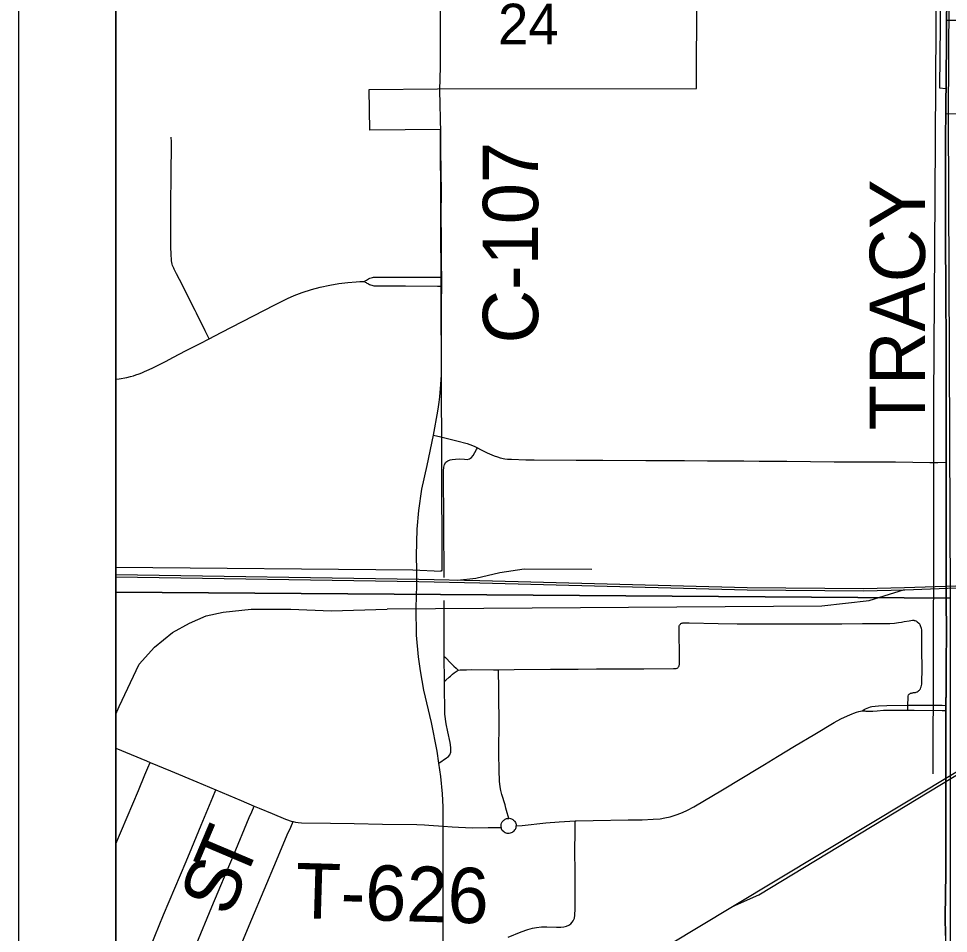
# Model space of a CAD drawing. Extents: x 0 to 40.2, y 0 to 22.
# Drawn here: x 2 to 2.955, y 15.414 to 16.354 of the extents above; entities that cross this region are included whole.
import ezdxf

# ---------------------------------------------------------------- set-up
doc = ezdxf.new("R2010")
doc.units = 0
for name, color, linetype in [('GM_X_Adjacent_County', 7, 'Continuous'), ('GM_X_City_Street', 7, 'Continuous'), ('GM_X_Corporation', 7, 'Continuous'), ('GM_X_County_Road_Text', 7, 'Continuous'), ('GM_X_Major_Lake_Text', 7, 'Continuous'), ('GM_X_Major_River', 7, 'Continuous'), ('GM_X_Minor_Lake', 7, 'Continuous'), ('GM_X_Rail_Line', 7, 'Continuous'), ('GM_X_Rail_Line_Text', 7, 'Continuous'), ('GM_X_Township_Road', 7, 'Continuous'), ('GM_X_Unincorporated_Location', 7, 'Continuous')]:
    doc.layers.add(name, color=color, linetype=linetype)

msp = doc.modelspace()

# ---------------------------------------------------------------- linework, layer by layer
at = {"layer": 'GM_X_Adjacent_County'}
for p, q in [((2, 21), (2, 14)), ((2.1, 20.9), (2.1, 14.1))]:
    msp.add_line(p, q, dxfattribs=at)
at = {"layer": 'GM_X_Corporation'}
for points in [[(2.1, 17.42646), (2.1, 14.1), (8.77357, 14.1)], [(2.1, 17.42646), (2.1, 14.1)], [(2.1, 16.79991), (2.1, 15.79032), (2.40476, 15.78728), (2.43404, 15.78611), (2.43404, 15.78684), (2.43478, 15.78683), (2.43443, 15.90141), (2.43329, 16.2397), (2.36065, 16.23885), (2.36014, 16.2807), (2.43027, 16.28139), (2.69598, 16.28187), (2.69674, 16.47681)], [(2.94777, 16.47691), (2.94574, 16.28254), (2.95227, 16.28186), (2.95199, 16.25577), (3.76676, 16.25602)], [(2.95339, 16.38497), (2.95296, 16.35249), (2.95273, 16.33553), (2.95228, 16.2871), (2.95225, 16.26721), (2.95199, 16.25577), (2.95187, 16.23333), (2.95182, 16.20037), (2.95173, 16.16556), (2.95187, 16.13695), (2.95186, 16.10961), (2.95198, 16.09219), (2.95217, 16.06609), (2.95237, 16.02442), (2.95249, 16.00591), (2.95234, 15.98044), (2.95244, 15.92634), (2.95237, 15.89849), (2.95237, 15.89713), (2.95254, 15.84302), (2.95231, 15.82625), (2.9526, 15.80324), (2.95241, 15.7765), (2.95245, 15.76531), (2.95255, 15.74826), (2.95265, 15.73145), (2.95247, 15.68297), (2.95241, 15.66431), (2.95222, 15.64879), (2.95216, 15.64356), (2.95202, 15.63261), (2.95214, 15.59965), (2.95203, 15.58162), (2.95194, 15.57043), (2.95195, 15.56113), (2.9521, 15.55057), (2.95227, 15.5319), (2.95195, 15.47593), (2.95154, 15.43118), (2.95171, 15.41189)], [(2.95171, 15.41189), (2.95154, 15.43118), (2.95195, 15.47593), (2.95227, 15.5319), (2.9521, 15.55057), (2.95195, 15.56113), (2.95194, 15.57043), (2.95203, 15.58162), (2.95214, 15.59965), (2.95202, 15.63261), (2.95216, 15.64356), (2.95222, 15.64879), (2.95241, 15.66431), (2.95247, 15.68297), (2.95265, 15.73145), (2.95255, 15.74826), (2.95245, 15.76531), (2.95241, 15.7765), (2.9526, 15.80324), (2.95231, 15.82625), (2.95254, 15.84302), (2.95237, 15.89713), (2.95237, 15.89849), (2.95244, 15.92634), (2.95234, 15.98044), (2.95249, 16.00591), (2.95237, 16.02442), (2.95217, 16.06609), (2.95198, 16.09219), (2.95186, 16.10961), (2.95187, 16.13695), (2.95173, 16.16556), (2.95182, 16.20037), (2.95187, 16.23333), (2.95199, 16.25577), (2.95225, 16.26721), (2.95228, 16.2871), (2.95273, 16.33553), (2.95296, 16.35249), (2.95339, 16.38497)]]:
    msp.add_lwpolyline(points, dxfattribs=at)
for points in [[(2.1, 16.80277), (2.1, 15.76442), (2.95674, 15.75847), (2.95497, 16.25386), (2.95786, 16.79166), (2.43037, 16.80164), (2.18336, 16.80457)], [(2.1, 15.76442), (2.1, 14.73705), (2.95186, 14.72799), (2.9569, 15.35216), (2.95674, 15.75847)]]:
    msp.add_lwpolyline(points, close=True, dxfattribs=at)
at = {"layer": 'GM_X_Major_Lake_Text'}
for p, q in [((2.43347, 16.23638), (2.43269, 16.28015)), ((2.43444, 16.07892), (2.43447, 16.08806))]:
    msp.add_line(p, q, dxfattribs=at)
for points in [[(2.43269, 16.28015), (2.43307, 16.30392), (2.43326, 16.35242), (2.43329, 16.38726), (2.4336, 16.44451), (2.43381, 16.49825), (2.4338, 16.52494), (2.4338, 16.532), (2.43402, 16.54423)], [(2.95318, 16.35193), (2.95362, 16.38442), (2.95425, 16.45108), (2.95453, 16.4809)], [(2.95272, 16.30975), (2.95295, 16.33497), (2.95318, 16.35193)], [(2.95221, 16.25521), (2.95247, 16.26666), (2.95251, 16.28655), (2.95272, 16.30975)], [(2.9526, 15.89794), (2.95267, 15.92578), (2.95257, 15.97988), (2.95272, 16.00535), (2.95259, 16.02386), (2.95239, 16.06553), (2.95221, 16.09163), (2.95208, 16.10905), (2.95209, 16.1364), (2.95196, 16.16501), (2.95205, 16.19982), (2.9521, 16.23277), (2.95221, 16.25521)], [(2.43447, 16.08806), (2.43447, 16.09045), (2.43434, 16.09856), (2.43428, 16.12516), (2.43405, 16.15311), (2.43417, 16.17494), (2.4337, 16.21839), (2.43354, 16.23354), (2.43347, 16.23638)], [(2.43357, 15.9776), (2.43436, 15.98763), (2.43421, 16.00426), (2.43438, 16.02036), (2.43439, 16.06262), (2.43444, 16.07892)], [(2.4261, 15.92584), (2.4304, 15.95047), (2.43121, 15.95473), (2.43186, 15.95947), (2.43254, 15.96524), (2.43357, 15.9776)], [(2.40902, 15.78688), (2.40861, 15.80206), (2.40928, 15.82904), (2.41089, 15.8484), (2.41411, 15.8703), (2.41943, 15.89465), (2.4261, 15.92584)], [(2.95239, 15.64301), (2.95245, 15.64823), (2.95264, 15.66375), (2.9527, 15.68241), (2.95288, 15.7309), (2.95277, 15.74771), (2.95267, 15.76476), (2.95264, 15.77595), (2.95283, 15.80268), (2.95254, 15.82569), (2.95277, 15.84246), (2.9526, 15.89657), (2.9526, 15.89794)], [(2.43167, 15.58868), (2.4299, 15.60108), (2.42389, 15.63058), (2.41627, 15.66377), (2.4128, 15.68382), (2.41049, 15.69811), (2.40864, 15.72047), (2.4084, 15.74836), (2.40908, 15.77164), (2.40905, 15.78593), (2.40902, 15.78688)], [(2.95227, 15.49236), (2.9525, 15.53135), (2.95232, 15.55001), (2.95218, 15.56057), (2.95216, 15.56988), (2.95226, 15.58106), (2.95236, 15.59909), (2.95225, 15.63205), (2.95239, 15.64301)], [(2.43594, 15.52412), (2.43592, 15.54385), (2.43521, 15.55729), (2.43359, 15.57526), (2.43167, 15.58868)], [(2.43611, 15.33128), (2.43613, 15.33482), (2.43598, 15.34288), (2.4359, 15.35512), (2.43603, 15.371), (2.43613, 15.39253), (2.43611, 15.39426), (2.43608, 15.40007), (2.4361, 15.4325), (2.4361, 15.45678), (2.43608, 15.48352), (2.43594, 15.52412)], [(2.95169, 15.38228), (2.9517, 15.38523), (2.95194, 15.41133), (2.95177, 15.43062), (2.95218, 15.47537), (2.95227, 15.49236)]]:
    msp.add_lwpolyline(points, dxfattribs=at)
at = {"layer": 'GM_X_Major_River'}
for points in [[(2.1, 15.78256), (2.41111, 15.77776), (2.47365, 15.77642), (2.7481, 15.7691), (2.86744, 15.76821), (2.90983, 15.7691), (2.96246, 15.77114), (3.02699, 15.77592), (3.0768, 15.78058), (3.16141, 15.79096), (3.23516, 15.79872), (3.28544, 15.80337), (3.31766, 15.80631)], [(2.1, 15.78024), (2.41107, 15.77544), (2.47359, 15.7741), (2.74806, 15.76678), (2.86745, 15.76589), (2.9099, 15.76678), (2.96259, 15.76882), (3.02718, 15.77361), (3.07705, 15.77828), (3.16167, 15.78865), (3.23539, 15.79641), (3.28565, 15.80106), (3.31787, 15.804)], [(2.73307, 15.44158), (3.00774, 15.60692), (3.07593, 15.64698), (3.09014, 15.65567), (3.10501, 15.66541), (3.11383, 15.67212), (3.12225, 15.67896), (3.15989, 15.71489), (3.18687, 15.74082), (3.19833, 15.75109), (3.21241, 15.76241), (3.22754, 15.77228), (3.2411, 15.77991), (3.25702, 15.78689), (3.27821, 15.79412), (3.31787, 15.804)], [(2.45063, 15.77691), (2.4696, 15.77888), (2.49401, 15.78473), (2.51915, 15.78828), (2.58847, 15.78825)], [(2.37837, 15.7474), (2.82477, 15.75052), (2.87342, 15.75583), (2.90968, 15.76733)], [(2.1, 15.63917), (2.10334, 15.64705), (2.12397, 15.69038), (2.1395, 15.70801), (2.15794, 15.72306), (2.17542, 15.73253), (2.19265, 15.74005), (2.20989, 15.74393), (2.23877, 15.74685), (2.27955, 15.74709), (2.32082, 15.74515), (2.37859, 15.74685)], [(2.73307, 15.44158), (2.76006, 15.45365), (2.99281, 15.59457), (3.02351, 15.61101), (3.03378, 15.61623), (3.05722, 15.62588), (3.07561, 15.63176), (3.0905, 15.63553), (3.1098, 15.64031), (3.12938, 15.64389), (3.14629, 15.64619), (3.16008, 15.6472), (3.18922, 15.64831), (3.20966, 15.648)], [(2.1, 14.61932), (2.26141, 15.01317), (2.2895, 15.07553), (2.32112, 15.14229), (2.3457, 15.18621), (2.37995, 15.2231), (2.43965, 15.26499), (2.73307, 15.44158)]]:
    msp.add_lwpolyline(points, dxfattribs=at)
at = {"layer": 'GM_X_Minor_Lake'}
msp.add_lwpolyline([(2.94289, 16.76173), (2.94143, 16.68124), (2.94132, 16.55791), (2.94195, 16.34577), (2.94079, 16.17084), (2.93956, 15.96176), (2.93953, 15.81566), (2.93868, 15.57772)], dxfattribs=at)
at = {"layer": 'GM_X_Rail_Line'}
for p, q in [((2.4261, 15.92584), (2.43372, 15.92398)), ((2.43717, 15.67298), (2.43715, 15.69836))]:
    msp.add_line(p, q, dxfattribs=at)
for points in [[(2.43372, 15.92398), (2.45013, 15.91996), (2.46044, 15.91728), (2.46333, 15.9163), (2.46782, 15.9143), (2.47115, 15.91261)], [(2.43682, 15.77943), (2.43644, 15.889), (2.43677, 15.89283), (2.43743, 15.89566), (2.43877, 15.89783), (2.44076, 15.89933), (2.44309, 15.90033), (2.44526, 15.90082), (2.44875, 15.90116), (2.45308, 15.90133), (2.45775, 15.901), (2.46075, 15.90083), (2.46308, 15.9015), (2.46507, 15.90267), (2.46674, 15.90483), (2.47023, 15.911), (2.47115, 15.91261)], [(2.47115, 15.91261), (2.47437, 15.91098), (2.48126, 15.90766), (2.4883, 15.90458), (2.49162, 15.90337), (2.4946, 15.90253), (2.49925, 15.90151), (2.50204, 15.90117), (2.50629, 15.90093), (2.52099, 15.90055), (2.52956, 15.90046), (2.57249, 15.90022), (2.59985, 15.89999), (2.64402, 15.89965), (2.68383, 15.89959), (2.70746, 15.89944), (2.74478, 15.89922), (2.76033, 15.89898), (2.77153, 15.899), (2.78894, 15.89899), (2.83744, 15.89846), (2.86911, 15.89849), (2.9003, 15.89819), (2.91822, 15.89795), (2.93565, 15.89757), (2.94379, 15.89775), (2.9526, 15.89794)], [(2.43715, 15.69836), (2.43713, 15.7093), (2.43687, 15.75586)], [(2.49291, 15.68482), (2.50875, 15.685), (2.54608, 15.68525), (2.56163, 15.68526), (2.57469, 15.68536), (2.59335, 15.68571), (2.61637, 15.68586), (2.64188, 15.68586), (2.67234, 15.686), (2.67522, 15.68613), (2.67616, 15.68645), (2.67681, 15.68686), (2.67731, 15.68738), (2.67785, 15.68801), (2.67819, 15.68879), (2.67842, 15.68955), (2.67855, 15.69029), (2.67863, 15.69101), (2.67873, 15.69208), (2.67875, 15.6929), (2.6787, 15.69655), (2.67849, 15.7045), (2.67828, 15.71817), (2.67824, 15.72816), (2.67831, 15.72898), (2.67842, 15.72977), (2.67865, 15.73045), (2.679, 15.73108), (2.67949, 15.73166), (2.68007, 15.73216), (2.68059, 15.73253), (2.68123, 15.73277), (2.68201, 15.73294), (2.68853, 15.73286), (2.71845, 15.7324), (2.73772, 15.73205), (2.77069, 15.73191), (2.84534, 15.73209), (2.8665, 15.73223), (2.8746, 15.7323), (2.87895, 15.73232), (2.89445, 15.73234), (2.89935, 15.73265), (2.90359, 15.73325), (2.9065, 15.73375), (2.90944, 15.73425), (2.91445, 15.73511), (2.91801, 15.73559), (2.91908, 15.73561), (2.91975, 15.73554), (2.92039, 15.73539), (2.92135, 15.73501), (2.92203, 15.73458), (2.92283, 15.73399), (2.92438, 15.73268)], [(2.91309, 15.64832), (2.91327, 15.65617), (2.91335, 15.65702), (2.91345, 15.65774), (2.91387, 15.65886), (2.91437, 15.6596), (2.91502, 15.66022), (2.91581, 15.66066), (2.91678, 15.6609), (2.9175, 15.66104), (2.91832, 15.66118), (2.91901, 15.66127), (2.91994, 15.6614), (2.92101, 15.66155), (2.9218, 15.66172), (2.9228, 15.66212), (2.92385, 15.6628), (2.92448, 15.66334), (2.92493, 15.6638), (2.92539, 15.66437), (2.92597, 15.66532), (2.92656, 15.66648), (2.92685, 15.6674), (2.92713, 15.66868), (2.92731, 15.67001), (2.9274, 15.67324), (2.92765, 15.68389), (2.92731, 15.70696), (2.92749, 15.71878), (2.92745, 15.72448), (2.92735, 15.72591), (2.9271, 15.7271), (2.92688, 15.72812), (2.9266, 15.72898), (2.92625, 15.73), (2.92582, 15.73085), (2.92529, 15.73166), (2.92438, 15.73268)], [(2.43715, 15.69836), (2.4382, 15.69728), (2.44377, 15.69152), (2.4451, 15.69012), (2.44706, 15.68843), (2.44921, 15.68649), (2.45143, 15.68447)], [(2.43717, 15.67298), (2.43856, 15.67417), (2.4422, 15.67731), (2.4435, 15.67837), (2.44567, 15.68017), (2.44737, 15.68156), (2.44921, 15.68287), (2.45143, 15.68447)], [(2.45143, 15.68447), (2.45354, 15.68467), (2.45573, 15.68482), (2.4598, 15.68485), (2.46521, 15.68488), (2.4876, 15.68477), (2.49291, 15.68482)], [(2.50322, 15.53218), (2.5027, 15.53444), (2.50177, 15.53788), (2.50047, 15.54269), (2.4996, 15.54595), (2.49633, 15.55667), (2.49511, 15.56092), (2.49441, 15.56465), (2.49382, 15.57028), (2.49333, 15.5815), (2.49306, 15.59892), (2.49331, 15.63308), (2.4932, 15.65543), (2.49303, 15.6672), (2.49293, 15.68197), (2.49291, 15.68482)], [(2.43167, 15.58868), (2.4394, 15.59418), (2.44146, 15.59563), (2.44272, 15.59749), (2.44378, 15.60027), (2.44385, 15.60498), (2.44324, 15.61022), (2.44085, 15.62103), (2.43912, 15.62938), (2.43763, 15.63905), (2.43751, 15.64329), (2.43718, 15.66651), (2.43717, 15.67298)], [(2.91309, 15.64832), (2.92331, 15.64842), (2.94822, 15.64826), (2.95245, 15.64823)], [(2.76075, 15.58442), (2.76593, 15.58754), (2.77925, 15.59553), (2.79671, 15.60633), (2.81767, 15.61852), (2.83731, 15.63054), (2.84445, 15.63442), (2.85126, 15.63761), (2.85581, 15.63938), (2.8577, 15.64012), (2.8605, 15.6412), (2.86264, 15.64191), (2.86635, 15.64269)], [(2.86635, 15.64269), (2.86828, 15.64393), (2.86963, 15.64466), (2.87117, 15.64547), (2.873, 15.64618), (2.8746, 15.64669), (2.87614, 15.64696), (2.87964, 15.64733), (2.88294, 15.64768), (2.89162, 15.64811), (2.91309, 15.64832)], [(2.86635, 15.64269), (2.86884, 15.64248), (2.87007, 15.64237), (2.87102, 15.64232), (2.87283, 15.64221), (2.87496, 15.64219), (2.87722, 15.64233), (2.88158, 15.64276), (2.88798, 15.64324), (2.89976, 15.64336), (2.9129, 15.64321)], [(2.9129, 15.64321), (2.91295, 15.64435), (2.91307, 15.64753), (2.91309, 15.64832)], [(2.9129, 15.64321), (2.91967, 15.64313), (2.94839, 15.64302), (2.95239, 15.64301)], [(2.1, 15.60426), (2.13134, 15.59117), (2.13515, 15.58958)], [(2.1, 15.50615), (2.12304, 15.56079), (2.12978, 15.57699), (2.13282, 15.58412), (2.13515, 15.58958)], [(2.13515, 15.58958), (2.15597, 15.58089), (2.18294, 15.56962), (2.20239, 15.56144)], [(2.57147, 15.52962), (2.5725, 15.52967), (2.58993, 15.53012), (2.62601, 15.53054), (2.64029, 15.53064), (2.65143, 15.53117), (2.65881, 15.53183), (2.66365, 15.53259), (2.66904, 15.53385), (2.67609, 15.53606), (2.68185, 15.53825), (2.68688, 15.54055), (2.69337, 15.5441), (2.72276, 15.56158), (2.76075, 15.58442)], [(2.11637, 15.35476), (2.12441, 15.37381), (2.13531, 15.40025), (2.14876, 15.43303), (2.17216, 15.48791), (2.17774, 15.50174), (2.18759, 15.52524), (2.19935, 15.55402), (2.20239, 15.56144)], [(2.20239, 15.56144), (2.22845, 15.5505), (2.24193, 15.54483)], [(2.15563, 15.33834), (2.17219, 15.37826), (2.18227, 15.40234), (2.19843, 15.4414), (2.22072, 15.49407), (2.23691, 15.53312), (2.23936, 15.53884), (2.24193, 15.54483)], [(2.24193, 15.54483), (2.24693, 15.54273), (2.26029, 15.53711), (2.27404, 15.53143), (2.281, 15.529), (2.28197, 15.52877)], [(2.19461, 15.32179), (2.19881, 15.33179), (2.20803, 15.35286), (2.21442, 15.36773), (2.22821, 15.40173), (2.23958, 15.42864), (2.26476, 15.48889), (2.27585, 15.51523), (2.27942, 15.52314), (2.28197, 15.52877)], [(2.28197, 15.52877), (2.2845, 15.52819), (2.28692, 15.52779), (2.29054, 15.52763), (2.32016, 15.52713), (2.34462, 15.52672), (2.37382, 15.52626), (2.409, 15.52601), (2.41669, 15.52565), (2.42116, 15.52531), (2.43594, 15.52412)], [(2.49538, 15.52286), (2.49537, 15.52401), (2.4954, 15.525), (2.49552, 15.5258), (2.49587, 15.52718), (2.49623, 15.52791), (2.49668, 15.52863), (2.49745, 15.52954), (2.4982, 15.53026), (2.49885, 15.5308), (2.49966, 15.53132), (2.50038, 15.53171), (2.50096, 15.53195), (2.50187, 15.53214), (2.50322, 15.53218)], [(2.49538, 15.52286), (2.49552, 15.5219), (2.4959, 15.52078), (2.49666, 15.51987), (2.4978, 15.51885), (2.49863, 15.51825), (2.49948, 15.51773), (2.50043, 15.5173), (2.5013, 15.51708), (2.50199, 15.51695), (2.5028, 15.51687), (2.50379, 15.51696), (2.50507, 15.51713), (2.50623, 15.5175), (2.50718, 15.51795), (2.50796, 15.51855), (2.50884, 15.51933), (2.50959, 15.52025), (2.51015, 15.521), (2.51046, 15.52163), (2.51076, 15.52293), (2.51093, 15.52443)], [(2.50268, 15.41014), (2.51601, 15.41548), (2.52297, 15.41802), (2.52769, 15.41935), (2.53189, 15.42015), (2.53676, 15.42069), (2.54228, 15.4209), (2.55218, 15.42041), (2.55665, 15.42036), (2.55987, 15.4207), (2.56243, 15.42133), (2.56484, 15.42239), (2.56703, 15.42395), (2.56843, 15.42539), (2.5696, 15.42704), (2.57067, 15.42949), (2.57129, 15.43269), (2.57159, 15.43913), (2.57167, 15.4596), (2.57158, 15.47496), (2.57131, 15.50072), (2.57147, 15.5162), (2.57147, 15.5281), (2.57147, 15.52962)], [(2.50322, 15.53218), (2.50424, 15.5322), (2.50517, 15.53204), (2.50616, 15.53177), (2.50691, 15.53143), (2.50745, 15.53108), (2.50826, 15.53041), (2.50914, 15.52953), (2.50968, 15.5289), (2.51034, 15.52777), (2.51063, 15.52685), (2.51076, 15.52602), (2.51093, 15.52443)], [(2.51093, 15.52443), (2.51695, 15.52476), (2.54142, 15.52763), (2.55509, 15.52871), (2.57147, 15.52962)], [(2.43594, 15.52412), (2.44524, 15.52347), (2.45185, 15.52299), (2.46607, 15.52252), (2.48222, 15.52281), (2.48994, 15.5227), (2.49538, 15.52286)]]:
    msp.add_lwpolyline(points, dxfattribs=at)
at = {"layer": 'GM_X_Township_Road'}
msp.add_lwpolyline([(2.1, 20.9), (8.9, 20.9), (8.9, 14.1), (2.1, 14.1)], close=True, dxfattribs=at)
at = {"layer": 'GM_X_Unincorporated_Location'}
for points in [[(2.95318, 16.35193), (2.95825, 16.35192), (2.97535, 16.35186), (3.00891, 16.35186), (3.04748, 16.35163), (3.06303, 16.35162), (3.08851, 16.35144), (3.11335, 16.35155), (3.12949, 16.35128), (3.16929, 16.35149), (3.19233, 16.35152), (3.211, 16.35144)], [(2.19565, 16.02466), (2.19171, 16.03273), (2.18276, 16.05103), (2.18136, 16.05371), (2.16527, 16.08561), (2.16225, 16.09132), (2.16046, 16.09481), (2.15965, 16.09635), (2.15933, 16.09708), (2.15876, 16.09846), (2.15844, 16.09927), (2.15817, 16.10015), (2.15784, 16.10127), (2.15745, 16.10297), (2.15713, 16.10494), (2.157, 16.10635), (2.15688, 16.10762), (2.1567, 16.10973), (2.15659, 16.11214), (2.15652, 16.1145), (2.15648, 16.11609), (2.15648, 16.12036), (2.15647, 16.13002), (2.15646, 16.16829), (2.15664, 16.18736), (2.1567, 16.19652), (2.1567, 16.20196), (2.15687, 16.21608), (2.15687, 16.22688), (2.15678, 16.2317)], [(2.35504, 16.08345), (2.35595, 16.08422), (2.35713, 16.08497), (2.35818, 16.08559), (2.35935, 16.08629), (2.36075, 16.08703), (2.36219, 16.08746), (2.36343, 16.08775), (2.36449, 16.08793), (2.36562, 16.08803), (2.36681, 16.08815), (2.36819, 16.08815), (2.38852, 16.08807), (2.41019, 16.08808), (2.42653, 16.08806), (2.43006, 16.08806), (2.43447, 16.08806)], [(2.1, 15.98314), (2.10337, 15.98358), (2.11126, 15.98508), (2.11476, 15.98587), (2.11784, 15.98674), (2.12048, 15.9876), (2.12369, 15.98866), (2.12644, 15.98969), (2.12941, 15.99095), (2.13409, 15.99305), (2.13796, 15.99489), (2.14199, 15.99696), (2.15158, 16.00179), (2.15831, 16.00535), (2.1721, 16.01257), (2.18652, 16.01985), (2.19565, 16.02466), (2.20798, 16.03117), (2.26326, 16.05975), (2.27607, 16.0662), (2.28295, 16.0692), (2.29117, 16.07224), (2.30068, 16.07532), (2.30973, 16.07777), (2.3195, 16.0799), (2.32874, 16.08151), (2.33805, 16.08266), (2.34679, 16.08327), (2.35047, 16.0834), (2.35504, 16.08345)], [(2.35504, 16.08345), (2.35597, 16.0829), (2.35677, 16.08242), (2.35752, 16.08197), (2.35851, 16.08148), (2.35938, 16.081), (2.36046, 16.08049), (2.36149, 16.0801), (2.36274, 16.07971), (2.36375, 16.07944), (2.36465, 16.07925), (2.36583, 16.07916), (2.36722, 16.07915), (2.387, 16.07904), (2.3974, 16.07904), (2.43022, 16.07893), (2.43444, 16.07892)]]:
    msp.add_lwpolyline(points, dxfattribs=at)

# ---------------------------------------------------------------- texts
at = {"layer": 'GM_X_City_Street'}
msp.add_text('24', height=0.041856, rotation=0.00001, dxfattribs=at).set_placement((2.49228, 16.32701))
at = {"layer": 'GM_X_County_Road_Text'}
for s, height, rotation, p in [('T', 0.05682, 67.06759, (2.23095, 15.46475)), ('S', 0.05682, 67.82094, (2.21656, 15.42944)), ('T-626', 0.056818, 358.35149, (2.28362, 15.42973))]:
    msp.add_text(s, height=height, rotation=rotation, dxfattribs=at).set_placement(p)
at = {"layer": 'GM_X_Rail_Line_Text'}
for s, p in [('C-107', (2.5335, 16.01997)), ('TRACY', (2.93075, 15.9308))]:
    msp.add_text(s, height=0.056818, rotation=90, dxfattribs=at).set_placement(p)

doc.saveas('drawing.dxf')
